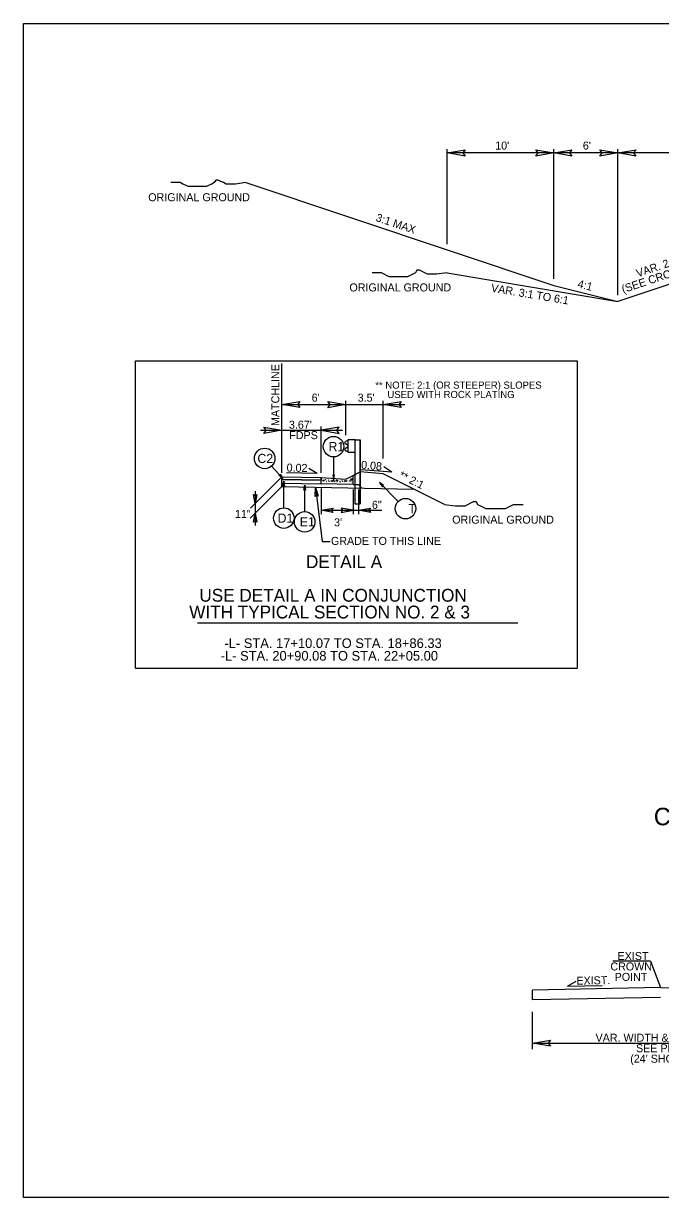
# Model space of a CAD drawing. Extents: x 1548135 to 1549339, y 868664 to 869085.
# Drawn here: x 1548135 to 1548194.7, y 868801.8 to 868911.8 of the extents above; entities that cross this region are included whole.
import ezdxf

# ---------------------------------------------------------------- set-up
doc = ezdxf.new("R2010")
doc.units = 0
for name, color, linetype in [('Default', 7, 'Continuous'), ('P_RDY_Shade_Light', 7, 'Continuous'), ('P_RDY_TC_Pvmt_Asphalt_Base_Course', 7, 'Continuous'), ('Prop Dimension', 7, 'Continuous'), ('Prop Dimension Text', 7, 'Continuous'), ('Prop Terminator CELL', 7, 'Continuous'), ('Sheet_Data_Field_CELL', 7, 'Continuous'), ('Sheet_Plan', 7, 'Continuous'), ('Sheet_Title_Block_Text', 7, 'Continuous'), ('Typical Grade Point Symbol CELL', 7, 'Continuous'), ('Typical Hinge Slope Arterial CELL', 7, 'Continuous'), ('Typical Hinge Slope Interstate CELL', 7, 'Continuous'), ('Typical Pavement Slope Information CELL', 7, 'Continuous'), ('Typical Shoulder Slope CELL', 7, 'Continuous'), ('Typical Slope Point Local CELL', 7, 'Continuous'), ('Typical Terminator CELL', 7, 'Continuous'), ('Typical Text Centerline CELL', 7, 'Continuous'), ('Typical Text General CELL', 7, 'Continuous'), ('Typical Text Grade Point CELL', 7, 'Continuous'), ('z - Construction', 7, 'Continuous')]:
    doc.layers.add(name, color=color, linetype=linetype)

msp = doc.modelspace()

# ---------------------------------------------------------------- linework, layer by layer
at = {"layer": 'Default'}
msp.add_lwpolyline([(1548135.05, 868911.82), (1548305.05, 868911.82), (1548305.05, 868801.82), (1548135.05, 868801.82)], close=True, dxfattribs=at)
at = {"layer": 'P_RDY_Shade_Light'}
for p, q in [((1548162.93, 868869.28), (1548162.93, 868869.28)), ((1548162.93, 868868.7), (1548162.93, 868869.27)), ((1548162.94, 868869.28), (1548165.26, 868869.14)), ((1548165.26, 868869.14), (1548165.93, 868869.47)), ((1548165.7, 868869.14), (1548165.71, 868869.05)), ((1548165.85, 868869.1), (1548165.7, 868869.14)), ((1548165.93, 868868.64), (1548165.93, 868869.47)), ((1548165.93, 868868.64), (1548162.93, 868868.7)), ((1548163.11, 868868.95), (1548163.19, 868869.07)), ((1548163.23, 868868.96), (1548163.11, 868868.95)), ((1548163.19, 868869.07), (1548163.23, 868868.96)), ((1548163.87, 868868.9), (1548163.93, 868869.01)), ((1548164.04, 868868.94), (1548163.87, 868868.9)), ((1548163.93, 868869.01), (1548164.04, 868868.94)), ((1548164.36, 868868.95), (1548164.44, 868869.07)), ((1548164.47, 868868.96), (1548164.36, 868868.95)), ((1548164.44, 868869.07), (1548164.47, 868868.96)), ((1548165.12, 868868.9), (1548165.18, 868869.01)), ((1548165.29, 868868.94), (1548165.12, 868868.9)), ((1548165.18, 868869.01), (1548165.29, 868868.94)), ((1548165.71, 868869.05), (1548165.85, 868869.1))]:
    msp.add_line(p, q, dxfattribs=at)
for centre in [(1548163, 868869.16), (1548165.82, 868869.18), (1548162.96, 868869.04), (1548163.36, 868869.09), (1548163.42, 868868.91), (1548163.48, 868868.88), (1548163.51, 868869), (1548163.59, 868869), (1548163.64, 868869.03), (1548163.68, 868868.92), (1548163.88, 868868.96), (1548164.08, 868868.94), (1548164.1, 868868.99), (1548164.11, 868869.05), (1548164.17, 868868.91), (1548164.26, 868868.95), (1548164.36, 868868.96), (1548164.48, 868868.91), (1548164.67, 868868.91), (1548164.73, 868868.88), (1548164.76, 868869), (1548164.89, 868869.03), (1548164.93, 868868.92), (1548165.13, 868868.96), (1548165.16, 868868.85), (1548165.33, 868868.94), (1548165.35, 868868.99), (1548165.61, 868868.96), (1548165.73, 868868.91)]:
    msp.add_circle(centre, 0.00802, dxfattribs=at)
msp.add_arc((1548162.94, 868869.27), 0.0104, 87.952, 180, dxfattribs=at)
at = {"layer": 'P_RDY_TC_Pvmt_Asphalt_Base_Course'}
for points in [[(1548176.43, 868899.4), (1548174.74, 868899.69), (1548176.44, 868899.99), (1548176.22, 868899.69)], [(1548183.05, 868899.98), (1548184.74, 868899.69), (1548183.04, 868899.39), (1548183.26, 868899.69)], [(1548186.43, 868899.4), (1548184.74, 868899.69), (1548186.44, 868899.99), (1548186.22, 868899.69)], [(1548189.05, 868899.98), (1548190.74, 868899.69), (1548189.04, 868899.39), (1548189.26, 868899.69)], [(1548192.43, 868899.4), (1548190.74, 868899.69), (1548192.44, 868899.99), (1548192.22, 868899.69)], [(1548160.95, 868875.83), (1548159.26, 868876.12), (1548160.95, 868876.42), (1548160.74, 868876.12)], [(1548163.57, 868876.41), (1548165.26, 868876.12), (1548163.56, 868875.82), (1548163.78, 868876.12)], [(1548170.45, 868875.83), (1548168.76, 868876.12), (1548170.45, 868876.42), (1548170.24, 868876.12)], [(1548157.57, 868874), (1548159.26, 868873.71), (1548157.56, 868873.41), (1548157.78, 868873.71)], [(1548164.62, 868874), (1548162.93, 868873.71), (1548164.62, 868873.41), (1548164.41, 868873.71)], [(1548164.05, 868866.01), (1548162.93, 868866.21), (1548164.06, 868866.41), (1548163.92, 868866.21)], [(1548164.8, 868866.01), (1548165.93, 868866.21), (1548164.8, 868866.41), (1548164.94, 868866.21)], [(1548167.55, 868866.01), (1548166.43, 868866.21), (1548167.56, 868866.41), (1548167.42, 868866.21)], [(1548184.42, 868815.99), (1548182.74, 868816.28), (1548184.43, 868816.58), (1548184.22, 868816.28)]]:
    msp.add_lwpolyline(points, close=True, dxfattribs=at)
at = {"layer": 'Prop Dimension'}
msp.add_lwpolyline([(1548174.49, 868866.77), (1548175.53, 868866.64), (1548175.79, 868866.64), (1548176.18, 868866.64), (1548176.43, 868866.64), (1548176.69, 868866.77), (1548176.95, 868866.9), (1548177.21, 868867.03), (1548177.47, 868867.03), (1548177.6, 868866.77), (1548177.86, 868866.64), (1548178.12, 868866.51), (1548178.38, 868866.38), (1548178.64, 868866.38), (1548178.9, 868866.38), (1548179.16, 868866.38), (1548179.42, 868866.38), (1548179.68, 868866.38), (1548179.94, 868866.38), (1548180.2, 868866.38), (1548180.45, 868866.51), (1548180.71, 868866.64), (1548180.97, 868866.77), (1548181.36, 868866.77), (1548181.62, 868866.77), (1548181.88, 868866.77)], dxfattribs=at)
at = {"layer": 'Prop Dimension Text'}
msp.add_line((1548159.26, 868869.11), (1548162.93, 868869.03), dxfattribs=at)
at = {"layer": 'Prop Terminator CELL'}
msp.add_lwpolyline([(1548159.26, 868869.36), (1548162.93, 868869.28), (1548162.93, 868869.03), (1548159.26, 868869.11)], close=True, dxfattribs=at)
at = {"layer": 'Sheet_Data_Field_CELL'}
for p, q in [((1548155.89, 868896.91), (1548184.74, 868887.29)), ((1548202.74, 868889.79), (1548190.74, 868885.79)), ((1548174.74, 868888.46), (1548190.74, 868885.79)), ((1548184.74, 868887.29), (1548190.74, 868885.79)), ((1548165.93, 868869.47), (1548166.61, 868869.81)), ((1548174.49, 868866.77), (1548168.76, 868869.63))]:
    msp.add_line(p, q, dxfattribs=at)
for points in [[(1548155.89, 868896.91), (1548154.9, 868896.78), (1548154.66, 868896.78), (1548154.29, 868896.78), (1548154.04, 868896.78), (1548153.8, 868896.91), (1548153.55, 868897.03), (1548153.3, 868897.15), (1548153.06, 868897.15), (1548152.93, 868896.91), (1548152.69, 868896.78), (1548152.44, 868896.66), (1548152.19, 868896.54), (1548151.95, 868896.54), (1548151.7, 868896.54), (1548151.45, 868896.54), (1548151.21, 868896.54), (1548150.96, 868896.54), (1548150.71, 868896.54), (1548150.47, 868896.54), (1548150.22, 868896.66), (1548149.98, 868896.78), (1548149.73, 868896.91), (1548149.36, 868896.91), (1548149.11, 868896.91), (1548148.87, 868896.91)], [(1548174.74, 868888.46), (1548173.75, 868888.33), (1548173.51, 868888.33), (1548173.14, 868888.33), (1548172.89, 868888.33), (1548172.64, 868888.46), (1548172.4, 868888.58), (1548172.15, 868888.7), (1548171.91, 868888.7), (1548171.78, 868888.46), (1548171.54, 868888.33), (1548171.29, 868888.21), (1548171.04, 868888.09), (1548170.8, 868888.09), (1548170.55, 868888.09), (1548170.3, 868888.09), (1548170.06, 868888.09), (1548169.81, 868888.09), (1548169.56, 868888.09), (1548169.32, 868888.09), (1548169.07, 868888.21), (1548168.83, 868888.33), (1548168.58, 868888.46), (1548168.21, 868888.46), (1548167.96, 868888.46), (1548167.72, 868888.46)]]:
    msp.add_lwpolyline(points, dxfattribs=at)
at = {"layer": 'Sheet_Plan'}
msp.add_line((1548168.76, 868869.63), (1548166.61, 868869.81), dxfattribs=at)
at = {"layer": 'Typical Grade Point Symbol CELL'}
for p, q in [((1548174.74, 868891.16), (1548174.74, 868900.04)), ((1548184.74, 868887.89), (1548184.74, 868900.04)), ((1548190.74, 868886.38), (1548190.74, 868900.04)), ((1548220.74, 868899.69), (1548174.74, 868899.69)), ((1548159.26, 868869.72), (1548159.26, 868879.97)), ((1548159.26, 868876.12), (1548165.26, 868876.12)), ((1548160.26, 868876.12), (1548162.26, 868876.12)), ((1548165.26, 868873.25), (1548165.26, 868876.48)), ((1548165.26, 868876.12), (1548170.77, 868876.12)), ((1548166.26, 868876.12), (1548168.26, 868876.12)), ((1548168.76, 868871.07), (1548168.76, 868876.48)), ((1548157.25, 868873.71), (1548164.94, 868873.71)), ((1548162.93, 868869.72), (1548162.93, 868874.07)), ((1548162.93, 868868.24), (1548162.93, 868865.85)), ((1548165.93, 868868.17), (1548165.93, 868865.85)), ((1548166.43, 868868.17), (1548166.43, 868865.85)), ((1548162.93, 868866.21), (1548165.93, 868866.21)), ((1548163.91, 868866.21), (1548165.91, 868866.21)), ((1548165.93, 868866.21), (1548168.63, 868866.21))]:
    msp.add_line(p, q, dxfattribs=at)
at = {"layer": 'Typical Hinge Slope Arterial CELL'}
msp.add_line((1548193.81, 868823.98), (1548190.26, 868823.98), dxfattribs=at)
at = {"layer": 'Typical Hinge Slope Interstate CELL'}
for p, q in [((1548158.29, 868870.35), (1548159.35, 868869.2)), ((1548164.1, 868871.22), (1548164.1, 868869.04)), ((1548156.31, 868866.41), (1548159.26, 868869.36)), ((1548156.3, 868865.49), (1548159.26, 868868.44)), ((1548156.75, 868868.01), (1548156.75, 868864.78)), ((1548159.44, 868866.44), (1548159.44, 868868.93)), ((1548161.4, 868866.09), (1548161.4, 868868.58)), ((1548170.16, 868867.05), (1548168.4, 868868.81)), ((1548145.54, 868851.43), (1548186.92, 868851.43)), ((1548194.74, 868821.5), (1548182.74, 868821.26)), ((1548182.74, 868820.34), (1548182.74, 868821.26)), ((1548194.74, 868821.5), (1548206.74, 868821.26)), ((1548194.74, 868820.58), (1548182.74, 868820.34))]:
    msp.add_line(p, q, dxfattribs=at)
for points in [[(1548145.54, 868851.43), (1548145.54, 868880.23), (1548186.92, 868880.23)], [(1548186.92, 868880.23), (1548186.92, 868851.43)], [(1548162.42, 868868.38), (1548163.02, 868863.3), (1548163.77, 868863.3)]]:
    msp.add_lwpolyline(points, dxfattribs=at)
for points in [[(1548159.09, 868869.6), (1548159.35, 868869.2), (1548158.97, 868869.49), (1548159.07, 868869.51)], [(1548164.02, 868869.51), (1548164.1, 868869.04), (1548164.18, 868869.52), (1548164.1, 868869.46)], [(1548159.35, 868868.46), (1548159.44, 868868.93), (1548159.52, 868868.45), (1548159.44, 868868.51)], [(1548161.32, 868868.11), (1548161.4, 868868.58), (1548161.48, 868868.11), (1548161.4, 868868.17)], [(1548162.37, 868867.52), (1548162.42, 868868.38), (1548162.67, 868867.55), (1548162.5, 868867.64)], [(1548168.79, 868868.54), (1548168.4, 868868.81), (1548168.68, 868868.42), (1548168.69, 868868.52)], [(1548156.9, 868867.7), (1548156.75, 868866.85), (1548156.6, 868867.7), (1548156.75, 868867.59)], [(1548156.61, 868865.09), (1548156.75, 868865.94), (1548156.9, 868865.09), (1548156.75, 868865.19)]]:
    msp.add_lwpolyline(points, close=True, dxfattribs=at)
for centre in [(1548164.1, 868872.18), (1548157.65, 868871.07), (1548170.84, 868866.37), (1548159.44, 868865.48), (1548161.4, 868865.13)]:
    msp.add_circle(centre, 0.962, dxfattribs=at)
at = {"layer": 'Typical Pavement Slope Information CELL'}
for p, q in [((1548169.57, 868869.77), (1548168.82, 868870.29)), ((1548162.57, 868869.65), (1548159.68, 868869.71)), ((1548162.57, 868869.65), (1548161.79, 868870.12)), ((1548169.57, 868869.77), (1548166.69, 868870.01)), ((1548186.03, 868821.62), (1548186.82, 868822.09)), ((1548186.03, 868821.62), (1548189.26, 868821.69))]:
    msp.add_line(p, q, dxfattribs=at)
at = {"layer": 'Typical Shoulder Slope CELL'}
msp.add_line((1548193.81, 868823.98), (1548194.74, 868821.5), dxfattribs=at)
at = {"layer": 'Typical Slope Point Local CELL'}
for p, q in [((1548165.33, 868872.71), (1548165.2, 868872.61)), ((1548165.2, 868872.49), (1548165.4, 868872.34)), ((1548165.43, 868872.73), (1548165.35, 868872.72)), ((1548166.11, 868872.81), (1548165.44, 868872.81)), ((1548165.44, 868872.81), (1548165.44, 868871.65)), ((1548166.11, 868872.81), (1548166.61, 868872.81)), ((1548166.12, 868872.81), (1548166.11, 868872.81)), ((1548166.11, 868872.81), (1548166.11, 868866.81)), ((1548166.12, 868866.81), (1548166.12, 868872.81)), ((1548166.61, 868872.81), (1548166.59, 868872.81)), ((1548166.59, 868872.81), (1548166.59, 868866.81)), ((1548166.61, 868866.81), (1548166.61, 868872.81)), ((1548165.4, 868872.12), (1548165.2, 868871.97)), ((1548165.2, 868871.84), (1548165.33, 868871.75)), ((1548165.35, 868871.74), (1548165.43, 868871.73)), ((1548165.44, 868872.28), (1548165.44, 868872.23)), ((1548165.44, 868872.23), (1548165.44, 868872.18)), ((1548165.44, 868871.65), (1548166.11, 868871.65)), ((1548166.11, 868866.81), (1548166.61, 868866.81)), ((1548166.11, 868866.81), (1548166.12, 868866.81)), ((1548166.59, 868866.81), (1548166.61, 868866.81))]:
    msp.add_line(p, q, dxfattribs=at)
for centre, radius, start, end in [((1548165.24, 868872.55), 0.0787, 125.2976, 235.3478), ((1548165.35, 868872.69), 0.0328, 100, 125.2976), ((1548165.24, 868871.91), 0.0787, 124.6522, 234.7024), ((1548165.35, 868871.77), 0.0328, 234.7024, 260), ((1548165.36, 868872.28), 0.0787, 0.02, 55.3478), ((1548165.36, 868872.18), 0.0787, 304.6522, 359.98)]:
    msp.add_arc(centre, radius, start, end, dxfattribs=at)
at = {"layer": 'Typical Terminator CELL'}
for p, q in [((1548151.36, 868855.67), (1548181.36, 868855.67)), ((1548182.74, 868815.71), (1548182.74, 868819.21)), ((1548182.74, 868816.28), (1548206.74, 868816.28))]:
    msp.add_line(p, q, dxfattribs=at)
at = {"layer": 'Typical Text Grade Point CELL'}
for p, q in [((1548159.26, 868869.36), (1548162.93, 868869.28)), ((1548159.26, 868868.44), (1548159.26, 868869.36)), ((1548159.26, 868868.77), (1548162.93, 868868.7)), ((1548159.26, 868868.44), (1548171.64, 868868.19)), ((1548165.93, 868868.64), (1548166.43, 868868.63)), ((1548166.43, 868868.63), (1548166.76, 868868.29))]:
    msp.add_line(p, q, dxfattribs=at)

# ---------------------------------------------------------------- texts
at = {"layer": 'Sheet_Data_Field_CELL'}
for p in [(1548146.74, 868895.17), (1548165.59, 868886.72), (1548175.22, 868864.96)]:
    msp.add_text('ORIGINAL GROUND', height=0.75, dxfattribs=at).set_placement(p)
for s, rotation, p in [('3:1 MAX', 341.565, (1548168, 868893.33)), ('(SEE CROSS SECTIONS)', 18.435, (1548191.24, 868886.55)), ('VAR. 2:1 TO 4:1', 18.435, (1548192.6, 868888.04)), ('VAR. 3:1 TO 6:1', 350.5377, (1548178.82, 868886.7)), ('4:1', 345.9638, (1548186.91, 868887.1)), ('** 2:1', 333.4951, (1548170.16, 868869.27))]:
    msp.add_text(s, height=0.75, rotation=rotation, dxfattribs=at).set_placement(p)
at = {"layer": 'Sheet_Title_Block_Text'}
msp.add_text('C', height=1.64, dxfattribs=at).set_placement((1548194.11, 868836.7))
at = {"layer": 'Typical Hinge Slope Arterial CELL'}
for s, p in [('DETAIL A', (1548161.52, 868860.8)), ('  USE DETAIL A IN CONJUNCTION', (1548150.64, 868857.65)), ('  WITH TYPICAL SECTION NO. 2 & 3', (1548149.69, 868856.08))]:
    msp.add_text(s, height=1.2, dxfattribs=at).set_placement(p)
at = {"layer": 'Typical Hinge Slope Interstate CELL'}
msp.add_text('MATCHLINE', height=0.75, rotation=90, dxfattribs=at).set_placement((1548159.02, 868874.11))
for s, height, p in [('R1', 0.861, (1548163.63, 868871.75)), ('C2', 0.861, (1548156.97, 868870.64)), ('11"', 0.75, (1548154.86, 868865.49)), ('D1', 0.861, (1548158.86, 868865.05)), ('T', 0.861, (1548171.12, 868865.94)), ('E1', 0.861, (1548160.94, 868864.7)), ('GRADE TO THIS LINE', 0.75, (1548163.86, 868862.97))]:
    msp.add_text(s, height=height, dxfattribs=at).set_placement(p)
at = {"layer": 'Typical Pavement Slope Information CELL'}
for s, rotation, p in [('0.02', 358.8544, (1548159.7, 868869.84)), ('EXIST.', 1.1456, (1548186.86, 868821.76))]:
    msp.add_text(s, height=0.75, rotation=rotation, dxfattribs=at).set_placement(p)
at = {"layer": 'Typical Shoulder Slope CELL'}
for s, p in [("10'", (1548179.25, 868900.01)), ("6'", (1548187.46, 868900.01)), ("6'", (1548162.05, 868876.39)), ("3.5'", (1548166.36, 868876.39)), ('6"', (1548167.7, 868866.35)), ("3'", (1548164.15, 868864.71)), ('EXIST', (1548190.71, 868824.08)), ('CROWN', (1548190.04, 868823.1)), ('POINT', (1548190.44, 868822.12)), ('VAR. WIDTH & LOCATION', (1548188.65, 868816.42)), ("(24' SHOWN)", (1548191.9, 868814.46)), ('SEE PLANS', (1548192.44, 868815.44))]:
    msp.add_text(s, height=0.75, dxfattribs=at).set_placement(p)
at = {"layer": 'Typical Text Centerline CELL'}
for s, p in [("3.67'", (1548159.92, 868873.86)), ('FDPS', (1548159.95, 868872.88))]:
    msp.add_text(s, height=0.75, dxfattribs=at).set_placement(p)
at = {"layer": 'Typical Text General CELL'}
for s, height, p in [('** NOTE: 2:1 (OR STEEPER) SLOPES ', 0.6682, (1548168.01, 868877.61)), ('USED WITH ROCK PLATING', 0.6682, (1548169.15, 868876.73)), ('-L- STA. 17+10.07 TO STA. 18+86.33', 0.9039, (1548153.88, 868853.31)), ('-L- STA. 20+90.08 TO STA. 22+05.00', 0.9039, (1548153.53, 868852.13))]:
    msp.add_text(s, height=height, dxfattribs=at).set_placement(p)
at = {"layer": 'z - Construction'}
msp.add_text('0.08', height=0.75, rotation=355.2385, dxfattribs=at).set_placement((1548166.66, 868870.11))

doc.saveas('drawing.dxf')
